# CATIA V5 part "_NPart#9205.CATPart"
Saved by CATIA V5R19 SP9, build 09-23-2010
Part number: 66_Anneau élastique pour arbre, 90x3
Revision: ANY
Definition: UNKNOWN
Nomenclature: 66_Anneau élastique pour arbre, 90x3
Source: Unknown
Bounding box of the stored display mesh (mm): x -49.1 to 49.1, y -50.874 to 51.05, z -1.5 to 1.5
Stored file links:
  Y:\fin de projet cabestan poupee\_NPart#9205.CATPart
  Ass_arbre poupee_1.CATProduct
  Y:\bricolage cabestan\6_axe.CATPart
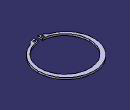
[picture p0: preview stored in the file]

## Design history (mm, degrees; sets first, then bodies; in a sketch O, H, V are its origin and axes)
Body1 "NONE" (main body)
  Solid1: solid without history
